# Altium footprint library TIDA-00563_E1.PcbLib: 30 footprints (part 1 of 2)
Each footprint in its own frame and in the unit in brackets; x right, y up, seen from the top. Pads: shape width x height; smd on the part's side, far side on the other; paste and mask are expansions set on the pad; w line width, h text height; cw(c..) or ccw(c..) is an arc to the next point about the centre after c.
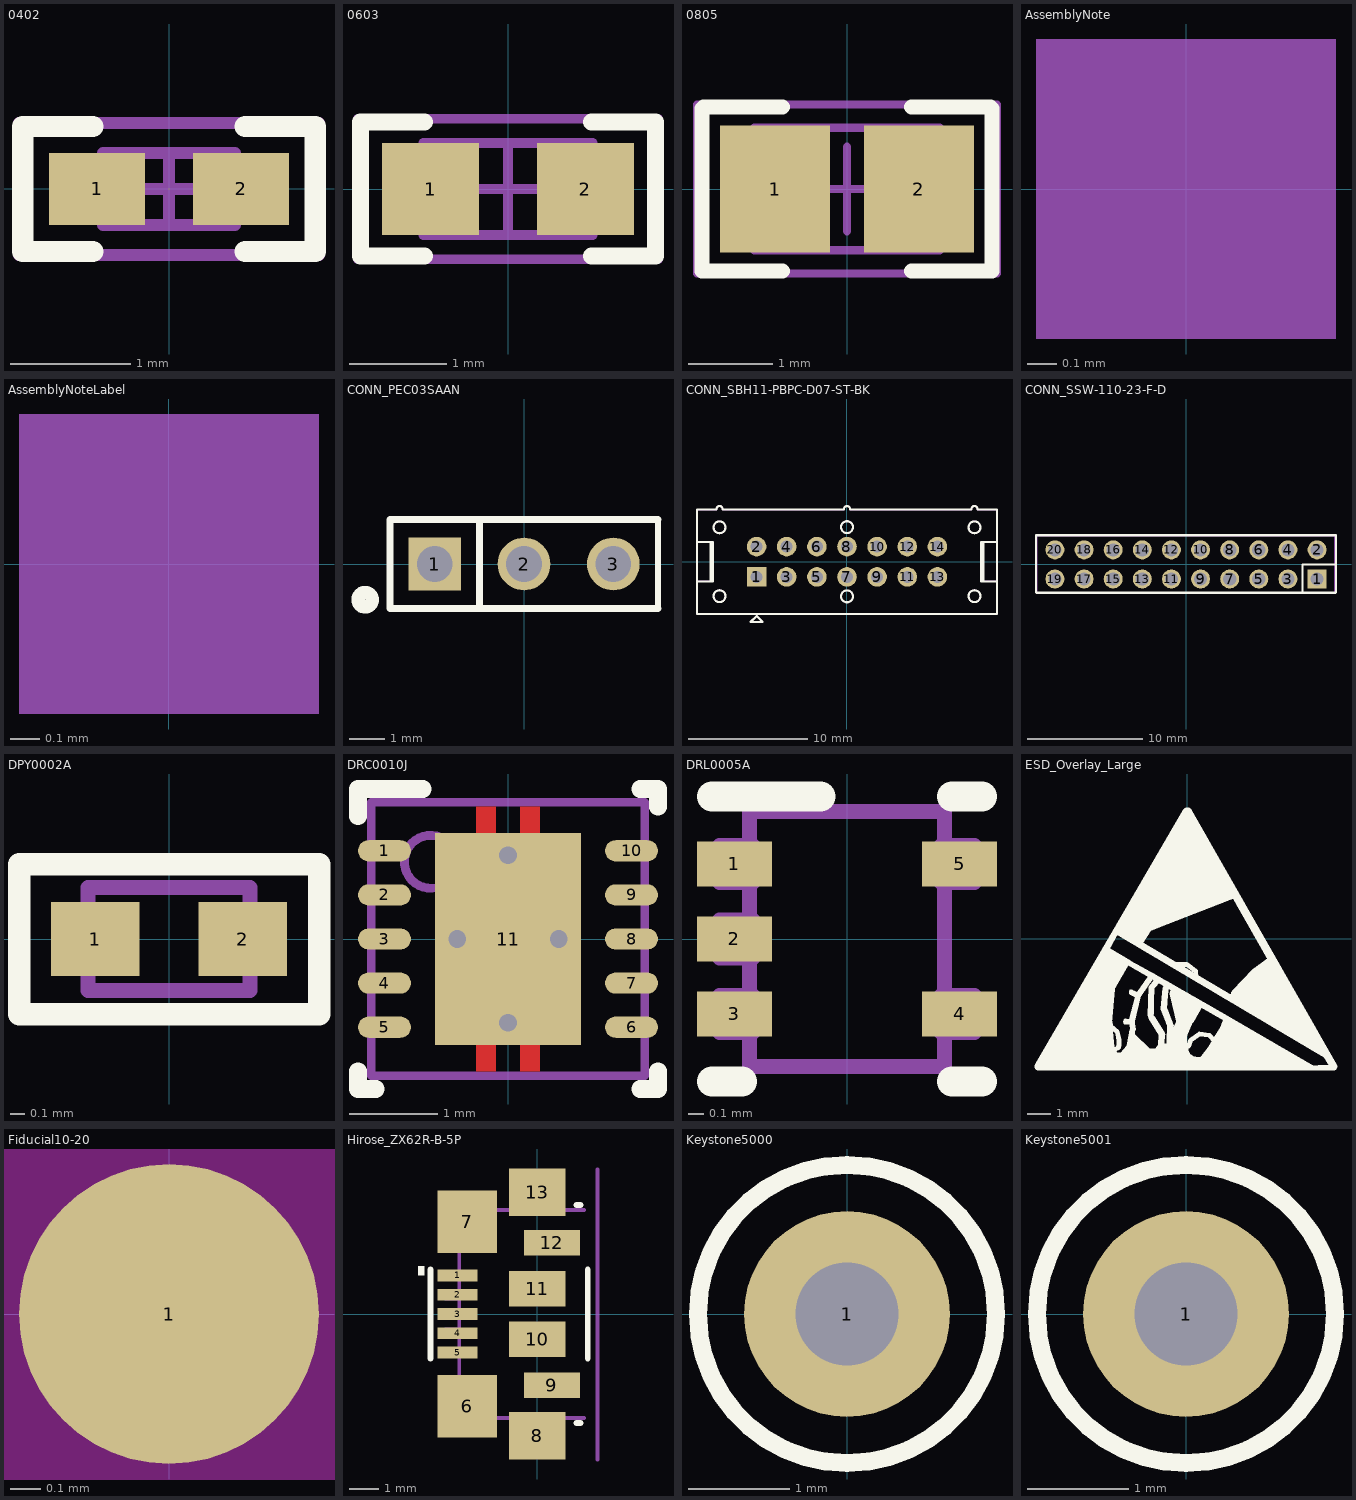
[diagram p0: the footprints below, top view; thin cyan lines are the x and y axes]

## 0402 [mm] "0402 from SM-752 data"
height 0.6
pads (2):
  rect 0.8x0.6 smd: 1(-0.6,0) 2(0.6,0)
Top Overlay:
  lines w0.178: -0.635,-0.521 -1.219,-0.521 -1.219,0.521 -0.635,0.521 ; 0.635,-0.521 1.219,-0.521 1.219,0.521 0.635,0.521
Mechanical 5:
  lines w0.1: -1.25,-0.55 1.25,-0.55 1.25,0.55 -1.25,0.55 -1.25,-0.55
  text ".Designator" at -0.711,-0.381 h0.64
Mechanical 13:
  lines w0.1: -0.35,-0.3 -0.35,0.3 ; 0.35,-0.3 0.35,0.3 ; -0.55,-0.3 -0.55,0.3 0.55,0.3 0.55,-0.3 -0.55,-0.3
Mechanical 15:
  lines w0.1: -0.3,0 0.3,0 ; 0,-0.3 0,0.3 ; -1.25,-0.55 -1.25,0.55 1.25,0.55 1.25,-0.55 -1.25,-0.55
3D body: height 0.6, standoff 0, extent -0.549,-0.299 -0.351,0.299
3D body: height 0.6, standoff 0, extent -0.349,-0.299 0.349,0.299
3D body: height 0.6, standoff 0, extent 0.351,-0.299 0.549,0.299

## 0603 [mm] "0603 from SM-752 data"
height 0.85
pads (2):
  rect 1x0.95 smd: 1(-0.8,0) 2(0.8,0)
Top Overlay:
  lines w0.178: -0.864,-0.691 -1.524,-0.691 -1.524,0.693 -0.864,0.693 ; 0.864,-0.691 1.524,-0.691 1.524,0.693 0.864,0.693
Mechanical 5:
  lines w0.1: -1.55,-0.725 1.55,-0.725 1.55,0.725 -1.55,0.725 -1.55,-0.725
  text ".Designator" at 0.787,0.33 h0.64
Mechanical 13:
  lines w0.1: -0.55,-0.475 -0.55,0.475 ; 0.55,-0.475 0.55,0.475 ; -0.875,-0.475 -0.875,0.475 0.875,0.475 0.875,-0.475 -0.875,-0.475
Mechanical 15:
  lines w0.1: -0.475,0 0.475,0 ; 0,-0.475 0,0.475 ; -1.55,-0.725 -1.55,0.725 1.55,0.725 1.55,-0.725 -1.55,-0.725
3D body: height 0.85, standoff 0, extent 0.551,-0.474 0.874,0.474
3D body: height 0.85, standoff 0, extent -0.549,-0.474 0.549,0.474
3D body: height 0.85, standoff 0, extent -0.874,-0.474 -0.551,0.474

## 0805 [mm] "0805 from SM-752 data"
height 1.1
pads (2):
  rect 1.3x1.5 smd: 1(-0.85,0) 2(0.85,0)
Top Overlay:
  lines w0.178: -0.762,-0.968 -1.717,-0.968 -1.717,0.95 -1.699,0.968 -0.762,0.968 ; 0.762,-0.968 1.717,-0.968 1.717,0.95 1.699,0.968 0.762,0.968
Mechanical 5:
  lines w0.1: -1.775,-1 -1.775,1 1.775,1 1.775,-1 -1.775,-1
  text ".Designator" at 0.635,0.33 h0.64
Mechanical 13:
  lines w0.1: -0.65,-0.725 -0.65,0.725 ; 0.65,-0.725 0.65,0.725 ; -1.1,-0.725 -1.1,0.725 1.1,0.725 1.1,-0.725 -1.1,-0.725
Mechanical 15:
  lines w0.1: -0.5,0 0.5,0 ; 0,-0.5 0,0.5 ; -1.775,-1 -1.775,1 1.775,1 1.775,-1 -1.775,-1
3D body: height 1.1, standoff 0, extent 0.651,-0.724 1.099,0.724
3D body: height 1.1, standoff 0, extent -0.649,-0.724 0.649,0.724
3D body: height 1.1, standoff 0, extent -1.099,-0.724 -0.651,0.724

## AssemblyNote [mm] "Assembly Note"
Mechanical 5:
  rectangle: -0.508,-0.508 0.508,0.508
  text ".Comment" at 1.143,-0.508 h0.64
  text ".Designator" at -4.191,-0.508 h0.64

## AssemblyNoteLabel [mm] "Assembly Note for PCB Labels"
Mechanical 5:
  rectangle: -0.508,-0.508 0.508,0.508
  text "Install label in silkscreened box after final wash.  Text shall be 8 pt font.  Text shall be per the Label Table in the PDF schematic." at 1.143,-0.508 h0.64
  text ".Designator" at -4.191,-0.508 h0.64

## CONN_PEC03SAAN [mm] "SULLINS"
height 8.38
pads (3):
  rect 1.5x1.5 hole 1.016: 1(-2.54,0)
  round 1.5 hole 1.016: 2(0,0) 3(2.54,0)
Top Overlay:
  circle w0.381: c-4.521,-1.016 r0.203
  lines w0.178: 3.81,-1.27 3.81,0.254 3.81,1.27
  lines w0.203: -1.27,1.27 -1.27,-1.27 ; 3.81,-1.27 -1.27,-1.27 ; 3.81,1.27 -3.81,1.27 -3.81,-1.27 -1.27,-1.27
Mechanical 5:
  rectangle: -3.048,-0.508 -2.032,0.508
  lines w0.127: -3.81,-1.27 3.81,-1.27 3.81,1.27 -3.81,1.27 -3.81,-1.27
  text ".Designator" at 0.61,0.356 h0.64
3D body: height 2.54, standoff 0, extent -3.835,-1.295 3.835,1.295
3D body: height 8.38, standoff -3.05, extent -2.844,-0.304 -2.236,0.304
3D body: height 8.38, standoff -3.05, extent -0.304,-0.304 0.304,0.304
3D body: height 8.38, standoff -3.05, extent 2.236,-0.304 2.844,0.304

## CONN_SBH11-PBPC-D07-ST-BK [mm] "Sullins recommended land pattern"
height 8.8
pads (14):
  rect 1.65x1.65 hole 1.016 mask+0.05: 1(-7.62,-1.27)
  round 1.65 hole 1.016 mask+0.05: 2(-7.62,1.27) 3(-5.08,-1.27) 4(-5.08,1.27) 5(-2.54,-1.27) 6(-2.54,1.27) 7(0,-1.27) 8(0,1.27) 9(2.54,-1.27) 10(2.54,1.27) 11(5.08,-1.27) 12(5.08,1.27) 13(7.62,-1.27) 14(7.62,1.27)
Top Overlay:
  lines w0.178: -11.49,-1.65 -11.49,1.65 ; 11.49,-1.65 11.49,1.65 ; -12.64,-1.65 -11.313,-1.65 -11.313,1.65 -12.64,1.65 ; -12.64,-1.65 -12.64,-4.4 12.64,-4.4 12.64,-1.65 ; -12.64,-1.65 -12.64,1.65 ; -12.64,1.65 -12.64,4.4 -10.99,4.4 -10.99,4.45 cw(c-10.74,4.45) -10.49,4.45 -10.49,4.4 -0.25,4.4 -0.25,4.45 cw(c0,4.45) 0.25,4.45 0.25,4.4 10.49,4.4 10.49,4.45 cw(c10.74,4.45) 10.99,4.45 10.99,4.4 12.64,4.4 12.64,1.65 ; 12.64,-1.65 11.314,-1.65 11.314,1.65 12.64,1.65 ; 12.64,-1.65 12.64,1.65 ; -10.74,-3.4 cw(c-10.74,-2.9) -10.74,-2.4 cw(c-10.74,-2.9) -10.74,-3.4 ; -10.74,2.4 cw(c-10.74,2.9) -10.74,3.4 cw(c-10.74,2.9) -10.74,2.4 ; -8.128,-5.08 -7.112,-5.08 -7.62,-4.572 -8.128,-5.08 ; 0,-3.417 cw(c0,-2.917) 0,-2.417 cw(c0,-2.917) 0,-3.417 ; 0,2.417 cw(c0,2.917) 0,3.417 cw(c0,2.917) 0,2.417 ; 10.74,-3.4 cw(c10.74,-2.9) 10.74,-2.4 cw(c10.74,-2.9) 10.74,-3.4 ; 10.74,2.4 cw(c10.74,2.9) 10.74,3.4 cw(c10.74,2.9) 10.74,2.4
Mechanical 5:
  lines w0.127: -11.49,-1.65 -11.49,1.65 ; 11.49,-1.65 11.49,1.65 ; -12.64,-1.65 -12.64,1.65 ; -12.64,-1.65 -12.64,-4.4 12.64,-4.4 12.64,-1.65 ; -12.64,-1.65 -11.313,-1.65 -11.313,1.65 -12.64,1.65 ; -12.64,1.65 -12.64,4.4 -10.99,4.4 -10.99,4.45 cw(c-10.74,4.45) -10.49,4.45 -10.49,4.4 -0.25,4.4 -0.25,4.45 cw(c0,4.45) 0.25,4.45 0.25,4.4 10.49,4.4 10.49,4.45 cw(c10.74,4.45) 10.99,4.45 10.99,4.4 12.64,4.4 12.64,1.65 ; 12.64,-1.65 12.64,1.65 ; 12.64,-1.65 11.314,-1.65 11.314,1.65 12.64,1.65 ; -10.74,-3.4 ccw(c-10.74,-2.9) -10.74,-2.4 ccw(c-10.74,-2.9) -10.74,-3.4 ; -10.74,2.4 ccw(c-10.74,2.9) -10.74,3.4 ccw(c-10.74,2.9) -10.74,2.4 ; -8.128,-5.08 -7.62,-4.572 -7.112,-5.08 -8.128,-5.08 ; 0,-3.417 ccw(c0,-2.917) 0,-2.417 ccw(c0,-2.917) 0,-3.417 ; 0,2.417 ccw(c0,2.917) 0,3.417 ccw(c0,2.917) 0,2.417 ; 10.74,-3.4 ccw(c10.74,-2.9) 10.74,-2.4 ccw(c10.74,-2.9) 10.74,-3.4 ; 10.74,2.4 ccw(c10.74,2.9) 10.74,3.4 ccw(c10.74,2.9) 10.74,2.4
  text ".Designator" at -0.737,-0.686 h0.64
3D body: height 9.12, standoff -2.68, extent -12.64,-4.4 12.64,4.7

## CONN_SSW-110-23-F-D [mm] "SAMTEC"
height 8.51
pads (20):
  rect 1.65x1.65 hole 1.15: 1(11.43,-1.27)
  round 1.65 hole 1.15: 2(11.43,1.27) 3(8.89,-1.27) 4(8.89,1.27) 5(6.35,-1.27) 6(6.35,1.27) 7(3.81,-1.27) 8(3.81,1.27) 9(1.27,-1.27) 10(1.27,1.27) 11(-1.27,-1.27) 12(-1.27,1.27) 13(-3.81,-1.27) 14(-3.81,1.27) 15(-6.35,-1.27) 16(-6.35,1.27) 17(-8.89,-1.27) 18(-8.89,1.27) 19(-11.43,-1.27) 20(-11.43,1.27)
Top Overlay:
  lines w0.203: -13.081,-2.438 -13.081,2.54 13.081,2.54 13.081,-2.413 ; -13.03,-2.464 13.03,-2.464 ; 10.16,-2.413 10.16,0 13.081,0
Mechanical 5:
  lines w0.1: -12.954,-2.464 12.954,-2.464 12.954,2.464 ; -12.954,0.076 -12.954,2.489 12.954,2.489
  lines w0.102: -12.954,-2.413 -12.954,0.127
  text ".Designator" at 13.614,0.762 h0.64
3D body: height 8.59, standoff -10.01, extent 3.518,0.953 4.153,1.588
3D body: height 8.59, standoff -10.01, extent 11.138,0.953 11.773,1.588
3D body: height 8.59, standoff -10.01, extent 8.573,0.953 9.208,1.588
3D body: height 8.59, standoff -10.01, extent 6.058,0.953 6.693,1.588
3D body: height 8.59, standoff -10.01, extent 0.953,0.953 1.588,1.588
3D body: height 8.59, standoff -10.01, extent -1.587,0.953 -0.952,1.588
3D body: height 8.59, standoff -10.01, extent -4.102,0.953 -3.467,1.588
3D body: height 8.59, standoff -10.01, extent -6.642,0.953 -6.007,1.588
3D body: height 8.59, standoff -10.01, extent -9.207,0.953 -8.572,1.588
3D body: height 8.59, standoff -10.01, extent -11.747,0.953 -11.112,1.588
3D body: height 8.59, standoff -10.01, extent -11.747,-1.587 -11.112,-0.952
3D body: height 8.59, standoff -10.01, extent -9.207,-1.587 -8.572,-0.952
3D body: height 8.59, standoff -10.01, extent -6.642,-1.587 -6.007,-0.952
3D body: height 8.59, standoff -10.01, extent -4.102,-1.587 -3.467,-0.952
3D body: height 8.59, standoff -10.01, extent -1.587,-1.587 -0.952,-0.952
3D body: height 8.59, standoff -10.01, extent 0.953,-1.587 1.588,-0.952
3D body: height 8.59, standoff -10.01, extent 6.058,-1.587 6.693,-0.952
3D body: height 8.59, standoff -10.01, extent 8.573,-1.587 9.208,-0.952
3D body: height 8.59, standoff -10.01, extent 11.138,-1.587 11.773,-0.952
3D body: height 8.59, standoff -10.01, extent 3.518,-1.587 4.153,-0.952
3D body: height 8.51, standoff 0, extent -13.005,-2.514 13.004,2.539

## DPY0002A [mm] "R-PX2SON-N2"
height 0.4
pads (2):
  rect 0.6x0.5 smd: 1(-0.5,0) 2(0.5,0)
Top Overlay:
  lines w0.152: -1.016,-0.508 1.016,-0.508 1.016,0.508 -0.762,0.508 -1.016,0.508 -1.016,-0.508
Mechanical 5:
  lines w0.102: -0.55,-0.35 0.55,-0.35 0.55,0.35 -0.55,0.35 -0.55,-0.35
  text ".Designator" at 0.533,-0.584 h0.64
3D body: height 0.4, standoff 0, extent -0.549,-0.349 0.549,0.349

## DRC0010J [mm] "SON, 10-Leads, Body 3x3mm, Pitch 0.5mm, Thermal Pad 2.4x1.65mm, TI Recommended"
height 1
pads (11):
  oval 0.6x0.24 smd: 1(-1.4,1) 2(-1.4,0.5) 3(-1.4,0) 4(-1.4,-0.5) 6(1.4,-1) 7(1.4,-0.5) 8(1.4,0) 9(1.4,0.5) 10(1.4,1)
  oval 0.6x0.24 smd mask+0.05: 5(-1.4,-1)
  rect 1.65x2.4 smd paste-0.825: 11(0,0)
via 0.575,0 diameter 0.5 hole 0.2
via -0.575,0 diameter 0.5 hole 0.2
via 0,0.95 diameter 0.5 hole 0.2
via 0,-0.95 diameter 0.5 hole 0.2
Top Layer:
  rectangle: 0.135,-1.5 0.365,-1.1
  region: -0.135,-1.1 -0.365,-1.1 -0.365,-1.5 -0.135,-1.5
  region: -0.135,1.5 -0.365,1.5 -0.365,1.1 -0.135,1.1
  rectangle: 0.135,1.1 0.365,1.5
Top Overlay:
  lines w0.2: -1.7,-1.5 -1.7,-1.7 -1.5,-1.7 ; -1.7,1.39 -1.7,1.7 -0.965,1.7 ; 1.5,-1.7 1.7,-1.7 1.7,-1.5 ; 1.5,1.7 1.7,1.7 1.7,1.5
Top Paste:
  rectangle: -0.75,0.1 0.75,1.165
  rectangle: -0.75,-1.165 0.75,-0.1
Mechanical 5:
  circle w0.1: c-0.875,0.875 r0.3
  lines w0.1: -1.55,-1.55 -1.55,1.55 1.55,1.55 1.55,-1.55 -1.55,-1.55
  text ".Designator" at 0.356,-0.61 h0.64
3D body: height 1, standoff 0, extent -1.55,-1.55 1.55,1.55
3D body: height 1.01, standoff 0.8, extent -1.18,0.57 -0.57,1.18

## DRL0005A [mm] "SOTFL, 5-Flat Leads, Body 1.2x1.6x0.6mm, Pitch 0.5mm, TI recommended"
height 0.6
pads (5):
  rect 0.5x0.3 smd: 1(-0.75,0.5) 2(-0.75,0) 3(-0.75,-0.5) 4(0.75,-0.5) 5(0.75,0.5)
Top Overlay:
  lines w0.2: -0.9,-0.95 -0.7,-0.95 ; -0.9,0.95 -0.175,0.95 ; 0.7,-0.95 0.9,-0.95 ; 0.7,0.95 0.9,0.95
Mechanical 5:
  lines w0.1: -0.65,-0.625 -0.65,-0.85 0.65,-0.85 0.65,-0.625 ; -0.65,-0.375 -0.65,-0.125 ; -0.65,0.125 -0.65,0.375 ; -0.65,0.625 -0.65,0.85 0.65,0.85 0.65,0.625 ; 0.65,-0.375 0.65,0.375 ; -0.85,-0.625 -0.627,-0.625 -0.627,-0.375 -0.85,-0.375 -0.85,-0.625 ; -0.85,-0.125 -0.85,0.125 -0.627,0.125 -0.627,-0.125 -0.85,-0.125 ; -0.85,0.375 -0.627,0.375 -0.627,0.625 -0.85,0.625 -0.85,0.375 ; 0.627,-0.625 0.85,-0.625 0.85,-0.375 0.627,-0.375 0.627,-0.625 ; 0.627,0.375 0.85,0.375 0.85,0.625 0.627,0.625 0.627,0.375
  text ".Designator" at -0.356,0.61 h0.64
3D body: height 0.62, standoff 0.02, extent -0.85,-0.85 0.85,0.85

## ESD_Overlay_Large [mm]
Top Overlay:
  drawing of 13628 lines, arcs and shapes, not listed

## Fiducial10-20 [mm]
pads (1):
  round 1 smd mask+0.5: 1(0,0)
Top Layer keep-out:
  circle w1.178: c0,0 r0.5

## Hirose_ZX62R-B-5P [mm] "Hirose"
height 2.65
pads (13):
  rect 1.35x0.4 smd: 1(-2.68,1.3) 2(-2.68,0.65) 3(-2.68,0) 4(-2.68,-0.65) 5(-2.68,-1.3)
  rect 2x2.1 smd: 6(-2.35,-3.1) 7(-2.35,3.1)
  rect 1.9x1.6 smd: 8(0,-4.1) 13(0,4.1)
  rect 1.88x0.85 smd: 9(0.495,-2.4) 12(0.495,2.4)
  rect 1.9x1.2 smd: 10(0,-0.85) 11(0,0.85)
Top Overlay:
  region: -4,1.6 -3.8,1.6 -3.8,1.3 -4,1.3
  lines w0.2: -3.6,-1.5 -3.6,1.5 ; 1.325,-3.675 1.45,-3.675 ; 1.325,3.675 1.45,3.675 ; 1.7,-1.5 1.7,1.5
Mechanical 1:
  lines w0.127: 2.032,-4.902 2.032,4.877
Mechanical 5:
  circle w0.254: c-2.1,2.8 r0.141
  lines w0.127: -2.65,-1.425 -3.1,-1.425 -3.1,-1.175 -2.65,-1.175 ; -2.65,-0.775 -3.1,-0.775 -3.1,-0.525 -2.65,-0.525 ; -2.65,-0.125 -3.1,-0.125 -3.1,0.125 -2.65,0.125 ; -2.65,0.525 -3.1,0.525 -3.1,0.775 -2.65,0.775 ; -2.65,1.175 -3.1,1.175 -3.1,1.425 -2.65,1.425 ; -0.425,-3.5 -0.425,-4.45 0.45,-4.45 0.45,-3.5 ; -0.425,3.5 -0.425,4.45 0.45,4.45 0.45,3.5 ; 1.575,-3.5 -2.625,-3.5 -2.625,3.5 1.575,3.5
  text ".Designator" at -0.94,0.991 h0.64
3D body: height 2.65, standoff 0, extent -2.565,-3.48 2.108,3.454
3D body: height 2.65, standoff 0, extent -2.253,2.647 -1.947,2.953

## Keystone5000 [mil] "For Keystone 500x miniature loop terminals"
height 181.1
pads (1):
  round 80 hole 40: 1(0,0)
Top Overlay:
  circle w7: c0,0 r58
Mechanical 5:
  circle w5: c0,0 r58.31
  text ".Designator" at -45,-10 h25
3D body: height 181.97, standoff -118.11, extent -49,-49 49.04,49.24

## Keystone5001 [mil] "For Keystone 500x miniature loop terminals"
height 181.1
pads (1):
  round 80 hole 40: 1(0,0)
Top Overlay:
  circle w7: c0,0 r58
Mechanical 5:
  circle w5: c0,0 r58.31
  text ".Designator" at -9,44 h25
3D body: height 181.97, standoff -118.11, extent -49,-49 49.04,49.24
